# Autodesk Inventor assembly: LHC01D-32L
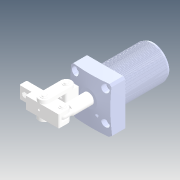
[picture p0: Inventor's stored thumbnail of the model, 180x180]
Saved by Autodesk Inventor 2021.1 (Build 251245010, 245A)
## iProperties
Created: 2019-04
Part Number: LHC01D-32L
Description: STEP AP214
Document SubType Name: Assembly
Designer: user
Title: LHC01D-32L.STEP
Revision Number: ÈÎºÎ
Sending System: SolidWorks 2016
Preprocessor: SwSTEP 2.0
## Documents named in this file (12)
- D:\Vault_2016\Projekty\Clamptek\Hydraulic\LHC01D\Inventor\LHC01D-32L\LHC01D-32L.iam
- D:\Vault_2016\Projekty\Clamptek\Hydraulic\LHC01D\Inventor\LHC01D-32L\LHC01D32L±¾Ìå.ipt
- D:\Vault_2016\Projekty\Clamptek\Hydraulic\LHC01D\Inventor\LHC01D-32L\LHC01D32»îÈû¸Ë.ipt
- D:\Vault_2016\Projekty\Clamptek\Hydraulic\LHC01D\Inventor\LHC01D-32L\4.ipt
- D:\Vault_2016\Projekty\Clamptek\Hydraulic\LHC01D\Inventor\LHC01D-32L\6.ipt
- D:\Vault_2016\Projekty\Clamptek\Hydraulic\LHC01D\Inventor\LHC01D-32L\7.ipt
- D:\Vault_2016\Projekty\Clamptek\Hydraulic\LHC01D\Inventor\LHC01D-32L\8.ipt
- D:\Vault_2016\Projekty\Clamptek\Hydraulic\LHC01D\Inventor\LHC01D-32L\10.ipt
- D:\Vault_2016\Projekty\Clamptek\Hydraulic\LHC01D\Inventor\LHC01D-32L\11.ipt
- D:\Vault_2016\Projekty\Clamptek\Hydraulic\LHC01D\Inventor\LHC01D-32L\12.ipt
- D:\Vault_2016\Projekty\Clamptek\Hydraulic\LHC01D\Inventor\LHC01D-32L\¶ÂÍ·_4.ipt
- D:\Vault_2016\Projekty\Clamptek\Hydraulic\LHC01D\Inventor\LHC01D-32L\5.ipt
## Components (28 placed, 28 different names)
1. LHC01D32L±¾Ìå_1
2. LHC01D32»îÈû¸Ë_2
3. 4_3
4. 6_4
5. 6_5
6. 7_6
7. 8_7
8. 10_8
9. 10_9
10. 10_10
11. 10_11
12. 10_12
13. 10_13
14. 11_14
15. 11_15
16. 11_16
17. 11_17
18. 11_18
19. 11_19
20. 12_20
21. 12_21
22. 12_22
23. 12_23
24. 12_24
25. 8_25
26. ¶ÂÍ·_4_26
27. ¶ÂÍ·_4_27
28. 5_28
